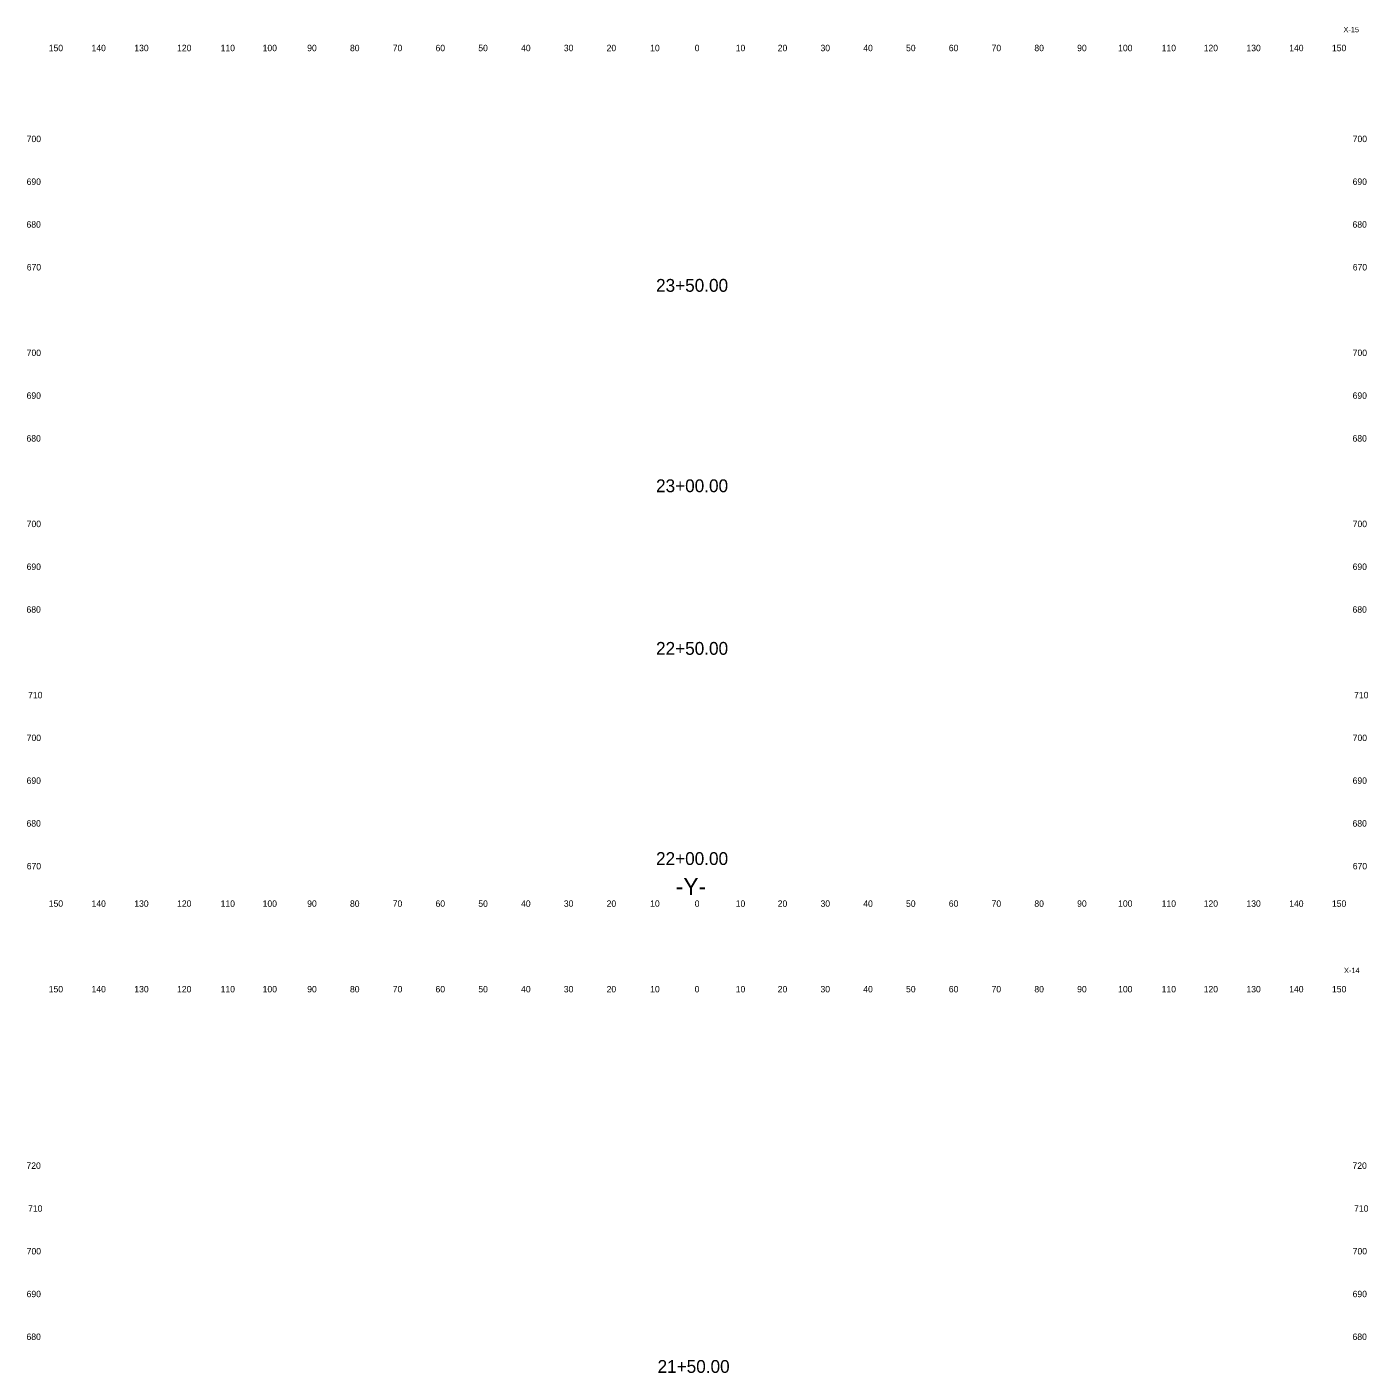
# Model space of a CAD drawing. Extents: x 3 to 317, y 1 to 1307.
# Drawn here: x 3.3 to 316.9, y 332.3 to 646.9 of the extents above; entities that cross this region are included whole.
import ezdxf

# ---------------------------------------------------------------- set-up
doc = ezdxf.new("R2010")
doc.units = 0
for name, color, linetype in [('Prop XS Alignment Label', 7, 'Continuous'), ('Prop XS Elevation Labels', 7, 'Continuous'), ('Prop XS Offset Labels', 7, 'Continuous'), ('Prop XS Sheet Number', 7, 'Continuous'), ('Prop XS Station Labels', 7, 'Continuous')]:
    doc.layers.add(name, color=color, linetype=linetype)

msp = doc.modelspace()

# ---------------------------------------------------------------- texts
at = {"layer": 'Prop XS Alignment Label'}
msp.add_text('-Y-', height=4, dxfattribs=at).set_placement((155, 444))
at = {"layer": 'Prop XS Elevation Labels'}
for s, p in [('700', (3.28, 620)), ('700', (313.28, 620)), ('690', (3.26, 610)), ('690', (313.26, 610)), ('680', (3.24, 600)), ('680', (313.24, 600)), ('670', (3.3, 590)), ('670', (313.3, 590)), ('700', (3.28, 570)), ('700', (313.28, 570)), ('690', (3.26, 560)), ('690', (313.26, 560)), ('680', (3.24, 550)), ('680', (313.24, 550)), ('700', (3.28, 530)), ('700', (313.28, 530)), ('690', (3.26, 520)), ('690', (313.26, 520)), ('680', (3.24, 510)), ('680', (313.24, 510)), ('710', (3.61, 490)), ('710', (313.61, 490)), ('700', (3.28, 480)), ('700', (313.28, 480)), ('690', (3.26, 470)), ('690', (313.26, 470)), ('680', (3.24, 460)), ('680', (313.24, 460)), ('670', (3.3, 450)), ('670', (313.3, 450)), ('720', (3.23, 380)), ('720', (313.23, 380)), ('710', (3.61, 370)), ('710', (313.61, 370)), ('700', (3.28, 360)), ('700', (313.28, 360)), ('690', (3.26, 350)), ('690', (313.26, 350)), ('680', (3.24, 340)), ('680', (313.24, 340))]:
    msp.add_text(s, height=1.5, dxfattribs=at).set_placement(p)
at = {"layer": 'Prop XS Offset Labels'}
for s, p in [('150', (8.44, 641.25)), ('140', (18.44, 641.25)), ('130', (28.44, 641.25)), ('120', (38.44, 641.25)), ('110', (48.62, 641.25)), ('100', (58.44, 641.25)), ('90', (68.86, 641.25)), ('80', (78.86, 641.25)), ('70', (88.86, 641.25)), ('60', (98.86, 641.25)), ('50', (108.86, 641.25)), ('40', (118.86, 641.25)), ('30', (128.86, 641.25)), ('20', (138.86, 641.25)), ('10', (149.04, 641.25)), ('0', (159.45, 641.25)), ('10', (169.04, 641.25)), ('20', (178.86, 641.25)), ('30', (188.86, 641.25)), ('40', (198.86, 641.25)), ('50', (208.86, 641.25)), ('60', (218.86, 641.25)), ('70', (228.86, 641.25)), ('80', (238.86, 641.25)), ('90', (248.86, 641.25)), ('100', (258.44, 641.25)), ('110', (268.62, 641.25)), ('120', (278.44, 641.25)), ('130', (288.44, 641.25)), ('140', (298.44, 641.25)), ('150', (308.44, 641.25)), ('150', (8.44, 441.25)), ('140', (18.44, 441.25)), ('130', (28.44, 441.25)), ('120', (38.44, 441.25)), ('110', (48.62, 441.25)), ('100', (58.44, 441.25)), ('90', (68.86, 441.25)), ('80', (78.86, 441.25)), ('70', (88.86, 441.25)), ('60', (98.86, 441.25)), ('50', (108.86, 441.25)), ('40', (118.86, 441.25)), ('30', (128.86, 441.25)), ('20', (138.86, 441.25)), ('10', (149.04, 441.25)), ('0', (159.45, 441.25)), ('10', (169.04, 441.25)), ('20', (178.86, 441.25)), ('30', (188.86, 441.25)), ('40', (198.86, 441.25)), ('50', (208.86, 441.25)), ('60', (218.86, 441.25)), ('70', (228.86, 441.25)), ('80', (238.86, 441.25)), ('90', (248.86, 441.25)), ('100', (258.44, 441.25)), ('110', (268.62, 441.25)), ('120', (278.44, 441.25)), ('130', (288.44, 441.25)), ('140', (298.44, 441.25)), ('150', (308.44, 441.25)), ('150', (8.44, 421.25)), ('140', (18.44, 421.25)), ('130', (28.44, 421.25)), ('120', (38.44, 421.25)), ('110', (48.62, 421.25)), ('100', (58.44, 421.25)), ('90', (68.86, 421.25)), ('80', (78.86, 421.25)), ('70', (88.86, 421.25)), ('60', (98.86, 421.25)), ('50', (108.86, 421.25)), ('40', (118.86, 421.25)), ('30', (128.86, 421.25)), ('20', (138.86, 421.25)), ('10', (149.04, 421.25)), ('0', (159.45, 421.25)), ('10', (169.04, 421.25)), ('20', (178.86, 421.25)), ('30', (188.86, 421.25)), ('40', (198.86, 421.25)), ('50', (208.86, 421.25)), ('60', (218.86, 421.25)), ('70', (228.86, 421.25)), ('80', (238.86, 421.25)), ('90', (248.86, 421.25)), ('100', (258.44, 421.25)), ('110', (268.62, 421.25)), ('120', (278.44, 421.25)), ('130', (288.44, 421.25)), ('140', (298.44, 421.25)), ('150', (308.44, 421.25))]:
    msp.add_text(s, height=1.5, dxfattribs=at).set_placement(p)
at = {"layer": 'Prop XS Sheet Number'}
for s, p in [('X-15', (311.12, 645.68)), ('X-14', (311.25, 425.75))]:
    msp.add_text(s, height=1.25, dxfattribs=at).set_placement(p)
at = {"layer": 'Prop XS Station Labels'}
for s, p in [('23+50.00', (150.41, 585.02)), ('23+00.00', (150.41, 538.17)), ('22+50.00', (150.41, 500.16)), ('22+00.00', (150.41, 451.03)), ('21+50.00', (150.77, 332.31))]:
    msp.add_text(s, height=3, dxfattribs=at).set_placement(p)

doc.saveas('drawing.dxf')
